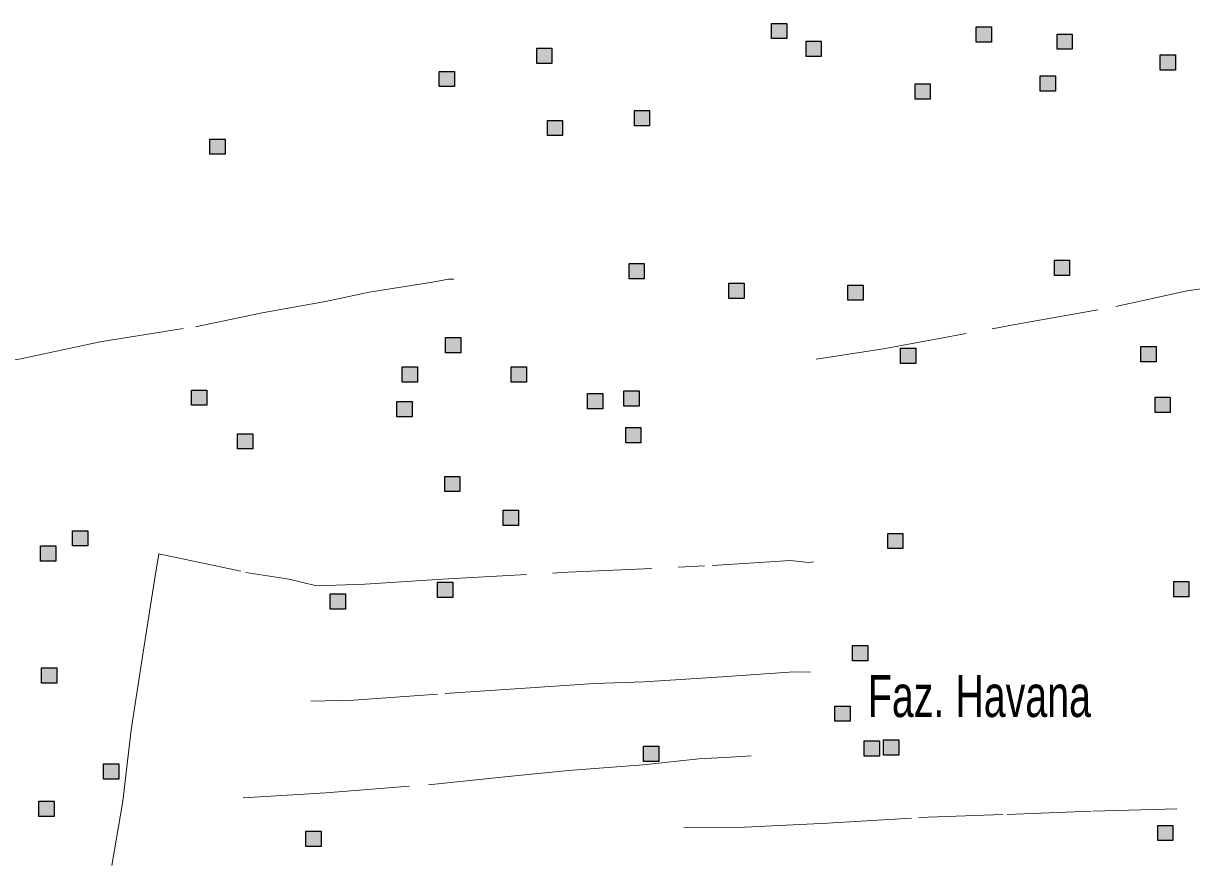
# Model space of a CAD drawing. Extents: x 445.6 to 500, y 8618.1 to 8673.4.
# Drawn here: x 492.441 to 496.888, y 8637.983 to 8641.188 of the extents above; entities that cross this region are included whole.
import ezdxf

# ---------------------------------------------------------------- set-up
doc = ezdxf.new("R2010")
doc.units = 0
doc.header["$LTSCALE"] = 0.064
doc.linetypes.add('DOT_DASHED', pattern=[7.7, 5, -1.2, 0.3, -1.2])
doc.layers.add('2', color=7, linetype='Continuous', lineweight=25)
doc.layers.add('22', color=7, linetype='DOT_DASHED', lineweight=13)
doc.layers.add('61', color=7, linetype='Continuous')

msp = doc.modelspace()

# ---------------------------------------------------------------- hatches: boundary and pattern name
at = {"layer": '2'}
for points in [[(495.2883, 8641.1882), (495.3463, 8641.1882), (495.3463, 8641.1302), (495.2883, 8641.1302)], [(496.0679, 8641.1747), (496.1259, 8641.1747), (496.1259, 8641.1167), (496.0679, 8641.1167)], [(496.3752, 8641.1476), (496.4332, 8641.1476), (496.4332, 8641.0896), (496.3752, 8641.0896)], [(495.42, 8641.1204), (495.478, 8641.1204), (495.478, 8641.0624), (495.42, 8641.0624)], [(494.3948, 8641.0935), (494.4528, 8641.0935), (494.4528, 8641.0355), (494.3948, 8641.0355)], [(496.7683, 8641.068), (496.8263, 8641.068), (496.8263, 8641.01), (496.7683, 8641.01)], [(494.0233, 8641.0055), (494.0813, 8641.0055), (494.0813, 8640.9475), (494.0233, 8640.9475)], [(496.3111, 8640.9884), (496.3691, 8640.9884), (496.3691, 8640.9304), (496.3111, 8640.9304)], [(495.8348, 8640.9579), (495.8928, 8640.9579), (495.8928, 8640.8999), (495.8348, 8640.8999)], [(494.7664, 8640.8564), (494.8244, 8640.8564), (494.8244, 8640.7984), (494.7664, 8640.7984)], [(494.4354, 8640.8191), (494.4934, 8640.8191), (494.4934, 8640.7611), (494.4354, 8640.7611)], [(493.1507, 8640.7479), (493.2087, 8640.7479), (493.2087, 8640.6899), (493.1507, 8640.6899)], [(494.7461, 8640.2737), (494.8041, 8640.2737), (494.8041, 8640.2157), (494.7461, 8640.2157)], [(496.3651, 8640.2871), (496.4231, 8640.2871), (496.4231, 8640.2291), (496.3651, 8640.2291)], [(495.1262, 8640.1989), (495.1842, 8640.1989), (495.1842, 8640.1409), (495.1262, 8640.1409)], [(495.5788, 8640.1922), (495.6368, 8640.1922), (495.6368, 8640.1342), (495.5788, 8640.1342)], [(494.0479, 8639.9924), (494.1059, 8639.9924), (494.1059, 8639.9344), (494.0479, 8639.9344)], [(495.7794, 8639.9518), (495.8374, 8639.9518), (495.8374, 8639.8938), (495.7794, 8639.8938)], [(496.6943, 8639.9585), (496.7523, 8639.9585), (496.7523, 8639.9005), (496.6943, 8639.9005)], [(493.8824, 8639.8806), (493.9404, 8639.8806), (493.9404, 8639.8226), (493.8824, 8639.8226)], [(494.2979, 8639.8806), (494.3559, 8639.8806), (494.3559, 8639.8226), (494.2979, 8639.8226)], [(493.0806, 8639.7925), (493.1386, 8639.7925), (493.1386, 8639.7345), (493.0806, 8639.7345)], [(494.5884, 8639.779), (494.6464, 8639.779), (494.6464, 8639.721), (494.5884, 8639.721)], [(494.7268, 8639.7892), (494.7848, 8639.7892), (494.7848, 8639.7312), (494.7268, 8639.7312)], [(496.7484, 8639.7654), (496.8064, 8639.7654), (496.8064, 8639.7074), (496.7484, 8639.7074)], [(493.8621, 8639.7485), (493.9201, 8639.7485), (493.9201, 8639.6905), (493.8621, 8639.6905)], [(493.2562, 8639.6265), (493.3142, 8639.6265), (493.3142, 8639.5685), (493.2562, 8639.5685)], [(494.7336, 8639.6503), (494.7916, 8639.6503), (494.7916, 8639.5923), (494.7336, 8639.5923)], [(494.0445, 8639.464), (494.1025, 8639.464), (494.1025, 8639.406), (494.0445, 8639.406)], [(494.2675, 8639.3353), (494.3255, 8639.3353), (494.3255, 8639.2773), (494.2675, 8639.2773)], [(492.628, 8639.2573), (492.686, 8639.2573), (492.686, 8639.1993), (492.628, 8639.1993)], [(495.7309, 8639.247), (495.7889, 8639.247), (495.7889, 8639.189), (495.7309, 8639.189)], [(492.5064, 8639.1997), (492.5644, 8639.1997), (492.5644, 8639.1417), (492.5064, 8639.1417)], [(494.0175, 8639.0609), (494.0755, 8639.0609), (494.0755, 8639.0029), (494.0175, 8639.0029)], [(496.8193, 8639.0641), (496.8773, 8639.0641), (496.8773, 8639.0061), (496.8193, 8639.0061)], [(493.6088, 8639.0168), (493.6668, 8639.0168), (493.6668, 8638.9588), (493.6088, 8638.9588)], [(495.597, 8638.8203), (495.655, 8638.8203), (495.655, 8638.7623), (495.597, 8638.7623)], [(492.5098, 8638.7355), (492.5678, 8638.7355), (492.5678, 8638.6775), (492.5098, 8638.6775)], [(495.5294, 8638.5899), (495.5874, 8638.5899), (495.5874, 8638.5319), (495.5294, 8638.5319)], [(494.8011, 8638.4375), (494.8591, 8638.4375), (494.8591, 8638.3795), (494.8011, 8638.3795)], [(495.6409, 8638.4578), (495.6989, 8638.4578), (495.6989, 8638.3998), (495.6409, 8638.3998)], [(495.7152, 8638.4612), (495.7732, 8638.4612), (495.7732, 8638.4032), (495.7152, 8638.4032)], [(492.7462, 8638.3696), (492.8042, 8638.3696), (492.8042, 8638.3116), (492.7462, 8638.3116)], [(492.4996, 8638.2274), (492.5576, 8638.2274), (492.5576, 8638.1694), (492.4996, 8638.1694)], [(496.7585, 8638.1358), (496.8165, 8638.1358), (496.8165, 8638.0778), (496.7585, 8638.0778)], [(493.5162, 8638.1137), (493.5742, 8638.1137), (493.5742, 8638.0557), (493.5162, 8638.0557)]]:
    msp.add_hatch(color=256, dxfattribs=at).paths.add_polyline_path(points)

# ---------------------------------------------------------------- linework, layer by layer
for points in [[(495.2883, 8641.1882), (495.3463, 8641.1882), (495.3463, 8641.1302), (495.2883, 8641.1302)], [(496.0679, 8641.1747), (496.1259, 8641.1747), (496.1259, 8641.1167), (496.0679, 8641.1167)], [(496.3752, 8641.1476), (496.4332, 8641.1476), (496.4332, 8641.0896), (496.3752, 8641.0896)], [(495.42, 8641.1204), (495.478, 8641.1204), (495.478, 8641.0624), (495.42, 8641.0624)], [(494.3948, 8641.0935), (494.4528, 8641.0935), (494.4528, 8641.0355), (494.3948, 8641.0355)], [(496.7683, 8641.068), (496.8263, 8641.068), (496.8263, 8641.01), (496.7683, 8641.01)], [(494.0233, 8641.0055), (494.0813, 8641.0055), (494.0813, 8640.9475), (494.0233, 8640.9475)], [(496.3111, 8640.9884), (496.3691, 8640.9884), (496.3691, 8640.9304), (496.3111, 8640.9304)], [(495.8348, 8640.9579), (495.8928, 8640.9579), (495.8928, 8640.8999), (495.8348, 8640.8999)], [(494.7664, 8640.8564), (494.8244, 8640.8564), (494.8244, 8640.7984), (494.7664, 8640.7984)], [(494.4354, 8640.8191), (494.4934, 8640.8191), (494.4934, 8640.7611), (494.4354, 8640.7611)], [(493.1507, 8640.7479), (493.2087, 8640.7479), (493.2087, 8640.6899), (493.1507, 8640.6899)], [(494.7461, 8640.2737), (494.8041, 8640.2737), (494.8041, 8640.2157), (494.7461, 8640.2157)], [(496.3651, 8640.2871), (496.4231, 8640.2871), (496.4231, 8640.2291), (496.3651, 8640.2291)], [(495.1262, 8640.1989), (495.1842, 8640.1989), (495.1842, 8640.1409), (495.1262, 8640.1409)], [(495.5788, 8640.1922), (495.6368, 8640.1922), (495.6368, 8640.1342), (495.5788, 8640.1342)], [(494.0479, 8639.9924), (494.1059, 8639.9924), (494.1059, 8639.9344), (494.0479, 8639.9344)], [(495.7794, 8639.9518), (495.8374, 8639.9518), (495.8374, 8639.8938), (495.7794, 8639.8938)], [(496.6943, 8639.9585), (496.7523, 8639.9585), (496.7523, 8639.9005), (496.6943, 8639.9005)], [(493.8824, 8639.8806), (493.9404, 8639.8806), (493.9404, 8639.8226), (493.8824, 8639.8226)], [(494.2979, 8639.8806), (494.3559, 8639.8806), (494.3559, 8639.8226), (494.2979, 8639.8226)], [(493.0806, 8639.7925), (493.1386, 8639.7925), (493.1386, 8639.7345), (493.0806, 8639.7345)], [(494.5884, 8639.779), (494.6464, 8639.779), (494.6464, 8639.721), (494.5884, 8639.721)], [(494.7268, 8639.7892), (494.7848, 8639.7892), (494.7848, 8639.7312), (494.7268, 8639.7312)], [(496.7484, 8639.7654), (496.8064, 8639.7654), (496.8064, 8639.7074), (496.7484, 8639.7074)], [(493.8621, 8639.7485), (493.9201, 8639.7485), (493.9201, 8639.6905), (493.8621, 8639.6905)], [(493.2562, 8639.6265), (493.3142, 8639.6265), (493.3142, 8639.5685), (493.2562, 8639.5685)], [(494.7336, 8639.6503), (494.7916, 8639.6503), (494.7916, 8639.5923), (494.7336, 8639.5923)], [(494.0445, 8639.464), (494.1025, 8639.464), (494.1025, 8639.406), (494.0445, 8639.406)], [(494.2675, 8639.3353), (494.3255, 8639.3353), (494.3255, 8639.2773), (494.2675, 8639.2773)], [(492.628, 8639.2573), (492.686, 8639.2573), (492.686, 8639.1993), (492.628, 8639.1993)], [(495.7309, 8639.247), (495.7889, 8639.247), (495.7889, 8639.189), (495.7309, 8639.189)], [(492.5064, 8639.1997), (492.5644, 8639.1997), (492.5644, 8639.1417), (492.5064, 8639.1417)], [(494.0175, 8639.0609), (494.0755, 8639.0609), (494.0755, 8639.0029), (494.0175, 8639.0029)], [(496.8193, 8639.0641), (496.8773, 8639.0641), (496.8773, 8639.0061), (496.8193, 8639.0061)], [(493.6088, 8639.0168), (493.6668, 8639.0168), (493.6668, 8638.9588), (493.6088, 8638.9588)], [(495.597, 8638.8203), (495.655, 8638.8203), (495.655, 8638.7623), (495.597, 8638.7623)], [(492.5098, 8638.7355), (492.5678, 8638.7355), (492.5678, 8638.6775), (492.5098, 8638.6775)], [(495.5294, 8638.5899), (495.5874, 8638.5899), (495.5874, 8638.5319), (495.5294, 8638.5319)], [(494.8011, 8638.4375), (494.8591, 8638.4375), (494.8591, 8638.3795), (494.8011, 8638.3795)], [(495.6409, 8638.4578), (495.6989, 8638.4578), (495.6989, 8638.3998), (495.6409, 8638.3998)], [(495.7152, 8638.4612), (495.7732, 8638.4612), (495.7732, 8638.4032), (495.7152, 8638.4032)], [(492.7462, 8638.3696), (492.8042, 8638.3696), (492.8042, 8638.3116), (492.7462, 8638.3116)], [(492.4996, 8638.2274), (492.5576, 8638.2274), (492.5576, 8638.1694), (492.4996, 8638.1694)], [(496.7585, 8638.1358), (496.8165, 8638.1358), (496.8165, 8638.0778), (496.7585, 8638.0778)], [(493.5162, 8638.1137), (493.5742, 8638.1137), (493.5742, 8638.0557), (493.5162, 8638.0557)]]:
    msp.add_lwpolyline(points, close=True, dxfattribs=at)
at = {"layer": '22'}
for points in [[(492.2015, 8639.8708), (492.3223, 8639.8942), (492.4305, 8639.9111), (492.6204, 8639.9519), (492.7334, 8639.9759), (493.0955, 8640.0337), (493.3503, 8640.0866), (493.5907, 8640.1298), (493.7566, 8640.1658), (493.9982, 8640.2026), (494.0583, 8640.2146), (494.0786, 8640.2152)], [(495.4581, 8639.9098), (495.7151, 8639.9499), (496.2153, 8640.0419), (496.5997, 8640.1103), (496.8708, 8640.1707), (497.0209, 8640.1918), (497.0525, 8640.1984)], [(492.7773, 8637.9826), (492.8197, 8638.2279), (492.8509, 8638.4996), (492.8906, 8638.7544), (492.9389, 8639.062), (492.9559, 8639.1695), (493.2875, 8639.0987), (493.4519, 8639.0733), (493.5567, 8639.0478), (493.741, 8639.0535), (494.0357, 8639.0733), (494.5136, 8639.0989), (495.0634, 8639.1244), (495.361, 8639.1442), (495.4308, 8639.1361), (495.4489, 8639.1389)], [(493.535, 8638.6087), (493.6979, 8638.6126), (494.0461, 8638.6377), (494.3313, 8638.6565), (494.6145, 8638.6754), (494.8033, 8638.6817), (495.1001, 8638.7008), (495.3728, 8638.7196), (495.4363, 8638.7193)], [(493.2777, 8638.2409), (493.592, 8638.2592), (493.9831, 8638.2903), (494.2864, 8638.3214), (494.5159, 8638.3441), (494.7994, 8638.3667), (495.0119, 8638.3894), (495.1326, 8638.3956), (495.2105, 8638.4002)], [(494.9553, 8638.1281), (495.1871, 8638.1292), (495.5016, 8638.1443), (495.8495, 8638.1654), (496.1852, 8638.1775), (496.5119, 8638.1896), (496.8369, 8638.1989)]]:
    msp.add_lwpolyline(points, dxfattribs=at)

# ---------------------------------------------------------------- texts
at = {"layer": '61', "width": 0.7}
msp.add_text('Faz. Havana', height=0.16, dxfattribs=at).set_placement((495.6553, 8638.5484))

doc.saveas('drawing.dxf')
